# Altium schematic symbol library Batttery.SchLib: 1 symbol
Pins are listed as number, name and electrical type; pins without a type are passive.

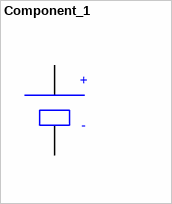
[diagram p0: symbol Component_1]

## Component_1
designator U?, comment Used in BOM report
SymbolVersion: use current date i.e. 2008-05-20; SymbolCreator: Use a-id; CompType: Used in some BOM reports.  Useful for finding later.; U/M: EA, IN, or GM
pins: 1, 2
